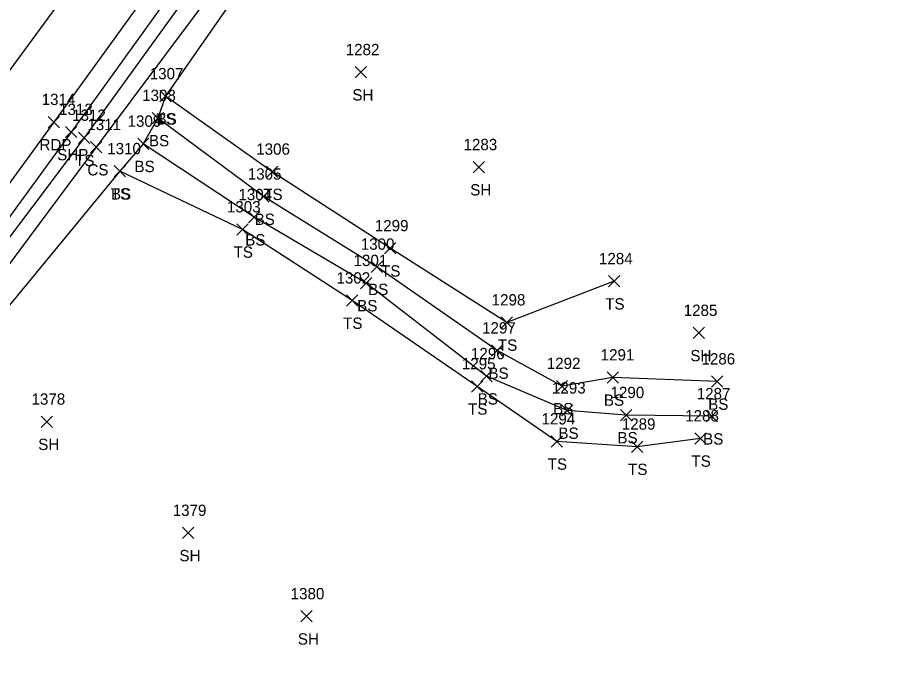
# Model space of a CAD drawing. Extents: x 1520648 to 1523413, y 732854 to 735518.
# Drawn here: x 1522552.4 to 1522704.9, y 734252.2 to 734369.1 of the extents above; entities that cross this region are included whole.
import ezdxf

# ---------------------------------------------------------------- set-up
doc = ezdxf.new("R2010")
doc.units = 0
for name, color, linetype in [('L_A', 7, 'Continuous'), ('L_I', 7, 'Continuous'), ('L_TIC', 7, 'Continuous'), ('LELB', 7, 'Continuous'), ('P_A', 7, 'Continuous'), ('P_I', 7, 'Continuous'), ('P_TIC', 7, 'Continuous'), ('PET', 7, 'Continuous'), ('PRC', 7, 'Continuous'), ('PSP', 7, 'Continuous')]:
    doc.layers.add(name, color=color, linetype=linetype)

msp = doc.modelspace()

# ---------------------------------------------------------------- linework, layer by layer
at = {"layer": 'L_TIC'}
for points in [[(1522612.1, 734358.43), (1522614.1, 734360.43)], [(1522614.1, 734358.43), (1522612.1, 734360.43)], [(1522577.57, 734354.18), (1522579.57, 734356.18)], [(1522579.57, 734354.18), (1522577.57, 734356.18)], [(1522577.57, 734354.18), (1522579.57, 734356.18)], [(1522579.57, 734354.18), (1522577.57, 734356.18)], [(1522576.23, 734350.34), (1522578.23, 734352.34)], [(1522578.23, 734350.34), (1522576.23, 734352.34)], [(1522576.23, 734350.34), (1522578.23, 734352.34)], [(1522578.23, 734350.34), (1522576.23, 734352.34)], [(1522563.23, 734346.84), (1522565.23, 734348.84)], [(1522565.23, 734346.84), (1522563.23, 734348.84)], [(1522573.67, 734345.79), (1522575.67, 734347.79)], [(1522575.67, 734345.79), (1522573.67, 734347.79)], [(1522573.67, 734345.79), (1522575.67, 734347.79)], [(1522575.67, 734345.79), (1522573.67, 734347.79)], [(1522565.34, 734345.2), (1522567.34, 734347.2)], [(1522567.34, 734345.2), (1522565.34, 734347.2)], [(1522569.51, 734340.94), (1522571.51, 734342.94)], [(1522571.51, 734340.94), (1522569.51, 734342.94)], [(1522569.51, 734340.94), (1522571.51, 734342.94)], [(1522571.51, 734340.94), (1522569.51, 734342.94)], [(1522596.44, 734340.86), (1522598.44, 734342.86)], [(1522598.44, 734340.86), (1522596.44, 734342.86)], [(1522632.91, 734341.66), (1522634.91, 734343.66)], [(1522634.91, 734341.66), (1522632.91, 734343.66)], [(1522594.89, 734336.46), (1522596.89, 734338.46)], [(1522596.89, 734336.46), (1522594.89, 734338.46)], [(1522593.23, 734332.83), (1522595.23, 734334.83)], [(1522595.23, 734332.83), (1522593.23, 734334.83)], [(1522591.21, 734330.67), (1522593.21, 734332.67)], [(1522593.21, 734330.67), (1522591.21, 734332.67)], [(1522617.25, 734327.34), (1522619.25, 734329.34)], [(1522619.25, 734327.34), (1522617.25, 734329.34)], [(1522614.93, 734324.08), (1522616.93, 734326.08)], [(1522616.93, 734324.08), (1522614.93, 734326.08)], [(1522613, 734321.2), (1522615, 734323.2)], [(1522615, 734321.2), (1522613, 734323.2)], [(1522656.83, 734321.52), (1522658.83, 734323.52)], [(1522658.83, 734321.52), (1522656.83, 734323.52)], [(1522610.55, 734318.11), (1522612.55, 734320.11)], [(1522612.55, 734318.11), (1522610.55, 734320.11)], [(1522637.88, 734314.24), (1522639.88, 734316.24)], [(1522639.88, 734314.24), (1522637.88, 734316.24)], [(1522671.79, 734312.39), (1522673.79, 734314.39)], [(1522673.79, 734312.39), (1522671.79, 734314.39)], [(1522636.18, 734309.29), (1522638.18, 734311.29)], [(1522638.18, 734309.29), (1522636.18, 734311.29)], [(1522634.28, 734304.75), (1522636.28, 734306.75)], [(1522636.28, 734304.75), (1522634.28, 734306.75)], [(1522656.57, 734304.53), (1522658.57, 734306.53)], [(1522658.57, 734304.53), (1522656.57, 734306.53)], [(1522632.61, 734302.96), (1522634.61, 734304.96)], [(1522634.61, 734302.96), (1522632.61, 734304.96)], [(1522647.61, 734303.02), (1522649.61, 734305.02)], [(1522649.61, 734303.02), (1522647.61, 734305.02)], [(1522674.99, 734303.82), (1522676.99, 734305.82)], [(1522676.99, 734303.82), (1522674.99, 734305.82)], [(1522648.54, 734298.69), (1522650.54, 734300.69)], [(1522650.54, 734298.69), (1522648.54, 734300.69)], [(1522556.62, 734296.72), (1522558.62, 734298.72)], [(1522558.62, 734296.72), (1522556.62, 734298.72)], [(1522658.96, 734297.89), (1522660.96, 734299.89)], [(1522660.96, 734297.89), (1522658.96, 734299.89)], [(1522674.09, 734297.68), (1522676.09, 734299.68)], [(1522676.09, 734297.68), (1522674.09, 734299.68)], [(1522672.06, 734293.77), (1522674.06, 734295.77)], [(1522674.06, 734293.77), (1522672.06, 734295.77)], [(1522646.68, 734293.23), (1522648.68, 734295.23)], [(1522648.68, 734293.23), (1522646.68, 734295.23)], [(1522660.87, 734292.31), (1522662.87, 734294.31)], [(1522662.87, 734292.31), (1522660.87, 734294.31)], [(1522581.56, 734277.08), (1522583.56, 734279.08)], [(1522583.56, 734277.08), (1522581.56, 734279.08)], [(1522602.47, 734262.36), (1522604.47, 734264.36)], [(1522604.47, 734262.36), (1522602.47, 734264.36)]]:
    msp.add_lwpolyline(points, dxfattribs=at)
at = {"layer": 'LELB'}
for points in [[(1522785.93, 734645.15), (1522756.48, 734606.7), (1522726.02, 734567.19), (1522697.44, 734525.1), (1522656.53, 734469.54), (1522622.12, 734421.12), (1522590.47, 734378.52), (1522566.34, 734346.2), (1522539.5, 734310.16), (1522511.43, 734266.75), (1522492.81, 734239.83), (1522459.56, 734196.4), (1522434.24, 734163.49), (1522417.99, 734140.69), (1522411.81, 734133.72), (1522406.56, 734130.49), (1522403.25, 734126.38), (1522401.8, 734120.85), (1522386.75, 734098.22)], [(1522693.92, 734527.21), (1522653.61, 734471.8), (1522618.94, 734423.11), (1522588.19, 734381.05), (1522564.23, 734347.84), (1522537.14, 734311.9), (1522506.92, 734269.19), (1522487.75, 734243.4), (1522455.5, 734199.63), (1522430.63, 734166.37), (1522416.02, 734145.08), (1522408.37, 734135.28), (1522403.01, 734129.97), (1522399.21, 734122.54), (1522383.71, 734100.99)], [(1522704.24, 734521.86), (1522660.18, 734466.65), (1522629.05, 734416.78), (1522593.47, 734376.61), (1522578.57, 734355.18), (1522577.23, 734351.34), (1522574.67, 734346.79), (1522570.51, 734341.94), (1522542.46, 734307.95), (1522517.77, 734263), (1522498.57, 734236.08), (1522463.16, 734193.34), (1522437.74, 734160.79), (1522421.27, 734139.69), (1522414.94, 734132.23), (1522411.1, 734128.72), (1522408.44, 734127.9), (1522407.08, 734128.93), (1522405.88, 734126.45), (1522406.78, 734124.9), (1522403.15, 734115.91), (1522392.7, 734094.89), (1522365.31, 734053.94)], [(1522657.83, 734322.52), (1522638.88, 734315.24), (1522618.25, 734328.34), (1522597.44, 734341.86), (1522578.57, 734355.18)], [(1522675.99, 734304.82), (1522657.57, 734305.53), (1522648.61, 734304.02), (1522637.18, 734310.29), (1522615.93, 734325.08), (1522595.89, 734337.46), (1522577.23, 734351.34)], [(1522675.09, 734298.68), (1522659.96, 734298.89), (1522649.54, 734299.69), (1522635.28, 734305.75), (1522614, 734322.2), (1522594.23, 734333.83), (1522574.67, 734346.79)], [(1522673.06, 734294.77), (1522661.87, 734293.31), (1522647.68, 734294.23), (1522633.61, 734303.96), (1522611.55, 734319.11), (1522592.21, 734331.67), (1522570.51, 734341.94)]]:
    msp.add_lwpolyline(points, dxfattribs=at)
at = {"layer": 'P_TIC'}
for points in [[(1522557.85, 734349.63), (1522559.85, 734351.63)], [(1522559.85, 734349.63), (1522557.85, 734351.63)], [(1522560.92, 734347.87), (1522562.92, 734349.87)], [(1522562.92, 734347.87), (1522560.92, 734349.87)]]:
    msp.add_lwpolyline(points, dxfattribs=at)
at = {"layer": 'PET'}
msp.add_lwpolyline([(1522887.76, 734807.39), (1522860.85, 734769.52), (1522801.36, 734686.8), (1522776.05, 734652.1), (1522748.04, 734612.12), (1522718.66, 734571.41), (1522688.63, 734530.01), (1522649.15, 734475.23), (1522613.31, 734425.7), (1522584.29, 734385.79), (1522558.85, 734350.63), (1522533.2, 734315.44), (1522501.29, 734271.61), (1522483.1, 734246.38), (1522451.17, 734203.52), (1522426.47, 734169.3), (1522405.75, 734141.77), (1522378.63, 734104.64)], dxfattribs=at)
at = {"layer": 'PRC'}
msp.add_lwpolyline([(1522878.51, 734813.79), (1522851.06, 734774.87), (1522817.97, 734729.86), (1522791.97, 734693.14), (1522766.66, 734657.61), (1522738.9, 734618.17), (1522708.24, 734576.9), (1522678.84, 734535.68), (1522640.14, 734482.21), (1522604.52, 734432.45), (1522576.44, 734394.44), (1522548.3, 734356.14), (1522523.72, 734322.36), (1522491.79, 734277.99), (1522474.03, 734253.33), (1522442.17, 734210.31), (1522417.88, 734177.66), (1522396.73, 734148.57), (1522369.92, 734111.45)], dxfattribs=at)
at = {"layer": 'PSP'}
msp.add_lwpolyline([(1522891.61, 734804.38), (1522863.83, 734767.51), (1522842.38, 734738.09), (1522825.83, 734714.72), (1522803.35, 734683.95), (1522778.9, 734649.79), (1522750.84, 734610.4), (1522721.18, 734569.96), (1522691.62, 734528.08), (1522651.91, 734473.19), (1522616.71, 734423.72), (1522586.83, 734383.52), (1522561.92, 734348.87), (1522535.83, 734313.09), (1522504.54, 734270.39), (1522485.78, 734244.5), (1522453.37, 734201.19), (1522428.68, 734167.53), (1522408.2, 734139.28), (1522381.04, 734102.47)], dxfattribs=at)

# ---------------------------------------------------------------- texts
at = {"layer": 'L_A'}
for s, p in [('SH', (1522611.59, 734354.43)), ('TS', (1522576.98, 734350.18)), ('BS', (1522577.01, 734350.18)), ('BS', (1522575.67, 734346.34)), ('BS', (1522575.67, 734346.34)), ('TS', (1522562.63, 734342.84)), ('CS', (1522564.79, 734341.2)), ('BS', (1522573.11, 734341.79)), ('BS', (1522573.11, 734341.79)), ('TS', (1522568.92, 734336.94)), ('BS', (1522568.95, 734336.94)), ('TS', (1522595.85, 734336.86)), ('SH', (1522632.4, 734337.66)), ('BS', (1522594.33, 734332.46)), ('BS', (1522592.67, 734328.83)), ('TS', (1522590.61, 734326.67)), ('TS', (1522616.66, 734323.34)), ('BS', (1522614.37, 734320.08)), ('BS', (1522612.44, 734317.2)), ('TS', (1522656.24, 734317.52)), ('TS', (1522609.96, 734314.11)), ('TS', (1522637.29, 734310.24)), ('SH', (1522671.28, 734308.39)), ('BS', (1522635.62, 734305.29)), ('BS', (1522633.72, 734300.75)), ('BS', (1522656.01, 734300.53)), ('BS', (1522674.43, 734299.82)), ('TS', (1522632.02, 734298.96)), ('BS', (1522647.05, 734299.02)), ('BS', (1522647.98, 734294.69)), ('BS', (1522658.4, 734293.89)), ('BS', (1522673.54, 734293.68)), ('SH', (1522556.11, 734292.72)), ('TS', (1522646.09, 734289.23)), ('TS', (1522671.47, 734289.77)), ('TS', (1522660.28, 734288.31)), ('SH', (1522581.05, 734273.08)), ('SH', (1522601.96, 734258.36))]:
    msp.add_text(s, height=2, dxfattribs=at).set_placement(p)
at = {"layer": 'L_I'}
for s, p in [('1282', (1522610.41, 734362.43)), ('1307', (1522575.8, 734358.18)), ('1307', (1522575.8, 734358.18)), ('1308', (1522574.46, 734354.34)), ('1308', (1522574.46, 734354.34)), ('1312', (1522562.1, 734350.84)), ('1311', (1522564.79, 734349.2)), ('1309', (1522571.89, 734349.79)), ('1309', (1522571.89, 734349.79)), ('1283', (1522631.22, 734345.66)), ('1310', (1522568.3, 734344.94)), ('1310', (1522568.3, 734344.94)), ('1306', (1522594.61, 734344.86)), ('1305', (1522593.12, 734340.46)), ('1304', (1522591.46, 734336.83)), ('1303', (1522589.43, 734334.67)), ('1299', (1522615.55, 734331.34)), ('1300', (1522613.07, 734328.08)), ('1301', (1522611.8, 734325.2)), ('1284', (1522655.14, 734325.52)), ('1302', (1522608.78, 734322.11)), ('1298', (1522636.19, 734318.24)), ('1285', (1522670.1, 734316.39)), ('1297', (1522634.49, 734313.29)), ('1296', (1522632.53, 734308.75)), ('1291', (1522655.44, 734308.53)), ('1286', (1522673.24, 734307.82)), ('1295', (1522630.92, 734306.96)), ('1292', (1522645.92, 734307.02)), ('1293', (1522646.84, 734302.69)), ('1290', (1522657.18, 734301.89)), ('1287', (1522672.4, 734301.68)), ('1378', (1522554.93, 734300.72)), ('1294', (1522644.99, 734297.23)), ('1288', (1522670.37, 734297.77)), ('1289', (1522659.17, 734296.31)), ('1379', (1522579.86, 734281.08)), ('1380', (1522600.69, 734266.36))]:
    msp.add_text(s, height=2, dxfattribs=at).set_placement(p)
at = {"layer": 'P_A'}
for s, p in [('RDP', (1522556.33, 734345.63)), ('SHP', (1522559.46, 734343.87))]:
    msp.add_text(s, height=2, dxfattribs=at).set_placement(p)
at = {"layer": 'P_I'}
for s, p in [('1314', (1522556.72, 734353.63)), ('1313', (1522559.8, 734351.87))]:
    msp.add_text(s, height=2, dxfattribs=at).set_placement(p)

doc.saveas('drawing.dxf')
